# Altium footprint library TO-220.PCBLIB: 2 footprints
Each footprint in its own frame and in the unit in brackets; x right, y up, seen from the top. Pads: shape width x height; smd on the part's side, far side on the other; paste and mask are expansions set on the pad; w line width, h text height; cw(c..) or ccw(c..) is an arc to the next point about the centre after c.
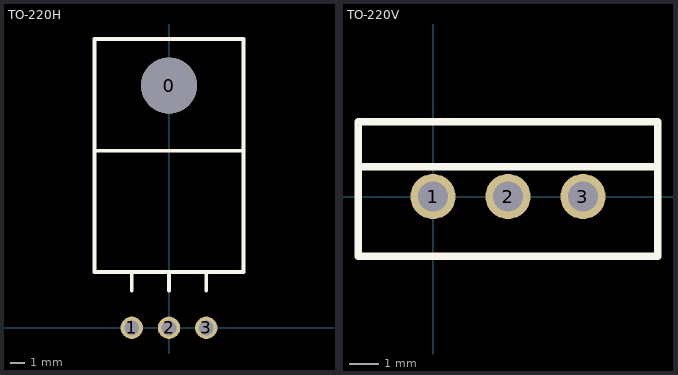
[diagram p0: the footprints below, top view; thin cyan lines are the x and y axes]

## TO-220H [mil]
pads (4):
  round 150 hole 150: 0(0,650)
  round 60 hole 40: 1(-100,0) 2(0,0) 3(100,0)
Top Overlay:
  lines w10: -200,475 200,475 ; -100,100 -100,150 ; 0,100 0,150 ; 100,100 100,150 ; -200,150 200,150 200,775 -200,775 -200,150

## TO-220V [mil]
pads (3):
  round 60 hole 40: 1(0,0) 2(100,0) 3(200,0)
Top Overlay:
  lines w10: -100,40 300,40 ; -100,-80 -100,100 300,100 300,-80 -100,-80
